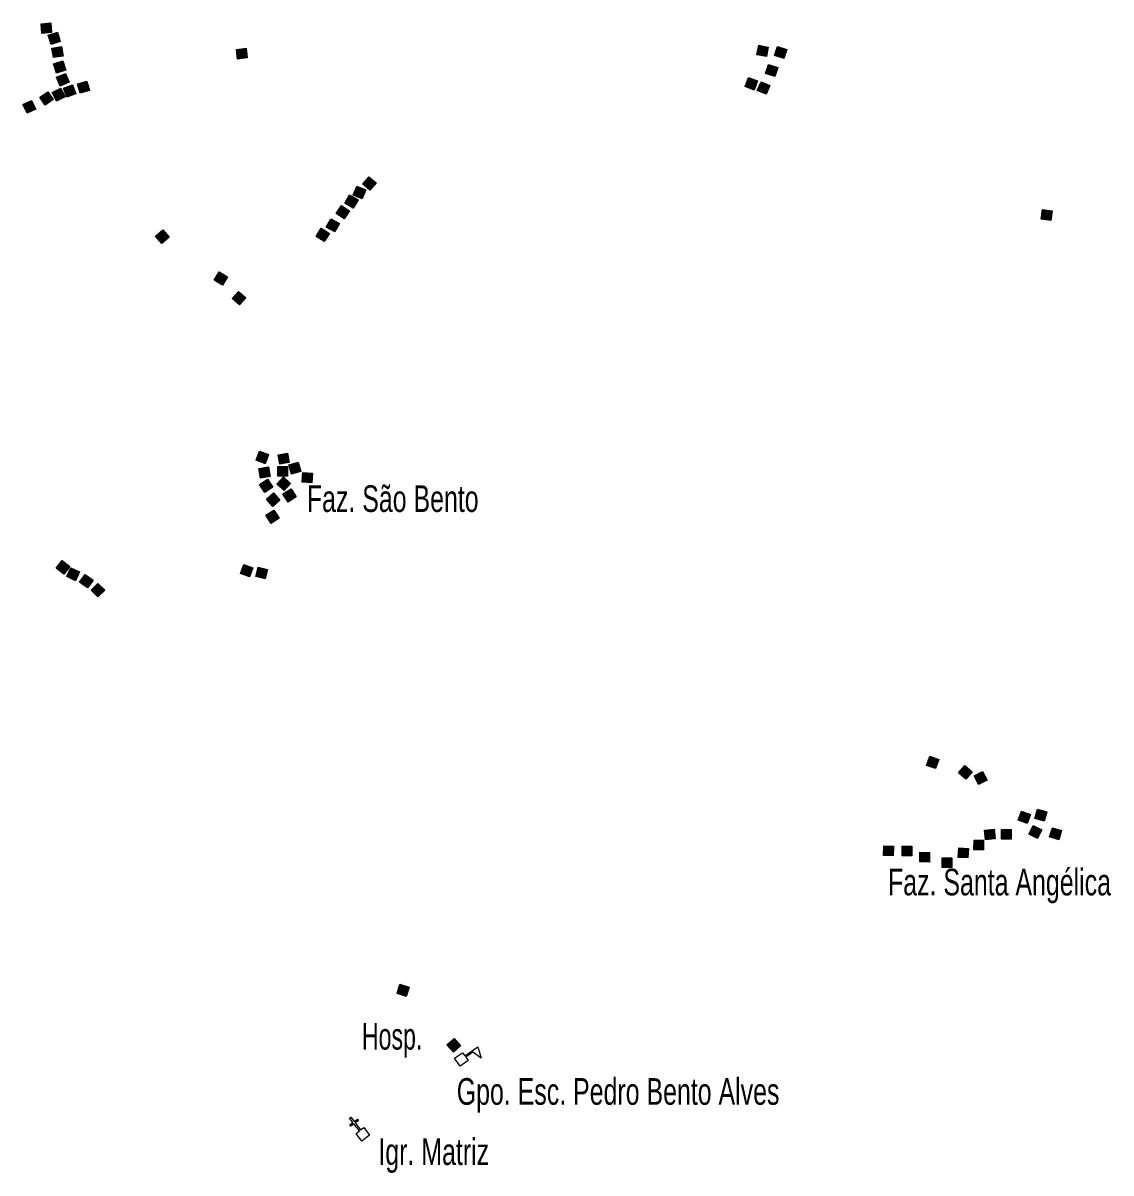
# Model space of a CAD drawing. Extents: x 679 to 705, y 7427.4 to 7455.4.
# Drawn here: x 698.263 to 701.533, y 7440.1 to 7443.555 of the extents above; entities that cross this region are included whole.
import ezdxf

# ---------------------------------------------------------------- set-up
doc = ezdxf.new("R2010")
doc.units = 0
doc.header["$LTSCALE"] = 0.032
for name, color, linetype, lineweight in [('2', 7, 'Continuous', 25), ('4', 7, 'Continuous', 25), ('6', 7, 'Continuous', 25)]:
    doc.layers.add(name, color=color, linetype=linetype, lineweight=lineweight)
doc.layers.add('61', color=7, linetype='Continuous')

msp = doc.modelspace()

# ---------------------------------------------------------------- hatches: boundary and pattern name
at = {"layer": '2'}
for points in [[(698.3468, 7443.5551), (698.3489, 7443.5261), (698.32, 7443.524), (698.3178, 7443.5529)], [(698.3672, 7443.5271), (698.3755, 7443.4992), (698.3477, 7443.491), (698.3394, 7443.5188)], [(698.3788, 7443.4843), (698.3836, 7443.4557), (698.355, 7443.451), (698.3502, 7443.4796)], [(698.9339, 7443.479), (698.9373, 7443.4502), (698.9085, 7443.4468), (698.9051, 7443.4756)], [(700.5033, 7443.4826), (700.4977, 7443.4542), (700.4692, 7443.4598), (700.4749, 7443.4882)], [(700.5587, 7443.4759), (700.5498, 7443.4483), (700.5222, 7443.4572), (700.5311, 7443.4848)], [(698.3826, 7443.4412), (698.3918, 7443.4137), (698.3643, 7443.4045), (698.3551, 7443.432)], [(700.5316, 7443.4216), (700.5227, 7443.394), (700.4951, 7443.403), (700.504, 7443.4306)], [(698.3906, 7443.4036), (698.4021, 7443.377), (698.3755, 7443.3654), (698.364, 7443.392)], [(700.4714, 7443.381), (700.4613, 7443.3538), (700.4341, 7443.3639), (700.4442, 7443.3911)], [(698.3767, 7443.3593), (698.3899, 7443.3335), (698.3641, 7443.3203), (698.3509, 7443.346)], [(698.4123, 7443.3697), (698.4224, 7443.3425), (698.3953, 7443.3324), (698.3851, 7443.3595)], [(698.4552, 7443.3802), (698.463, 7443.3523), (698.4351, 7443.3444), (698.4272, 7443.3723)], [(700.5084, 7443.3675), (700.4971, 7443.3408), (700.4704, 7443.352), (700.4817, 7443.3788)], [(698.2893, 7443.3225), (698.3021, 7443.2964), (698.276, 7443.2837), (698.2633, 7443.3098)], [(698.3375, 7443.3487), (698.354, 7443.3249), (698.3302, 7443.3084), (698.3137, 7443.3322)], [(699.3029, 7443.0934), (699.3249, 7443.0746), (699.306, 7443.0525), (699.284, 7443.0714)], [(699.2667, 7443.0648), (699.2935, 7443.0537), (699.2823, 7443.0269), (699.2555, 7443.0381)], [(699.245, 7443.0385), (699.2702, 7443.0242), (699.2559, 7442.999), (699.2307, 7443.0133)], [(699.2209, 7443.007), (699.245, 7442.9908), (699.2288, 7442.9667), (699.2047, 7442.9829)], [(701.3565, 7442.9903), (701.3525, 7442.9616), (701.3238, 7442.9656), (701.3278, 7442.9943)], [(699.1889, 7442.9666), (699.2143, 7442.9526), (699.2003, 7442.9272), (699.1749, 7442.9412)], [(698.6839, 7442.9339), (698.7028, 7442.912), (698.6809, 7442.893), (698.6619, 7442.915)], [(699.1597, 7442.9382), (699.1843, 7442.9228), (699.1688, 7442.8982), (699.1443, 7442.9137)], [(698.8533, 7442.8073), (698.8781, 7442.7922), (698.863, 7442.7675), (698.8382, 7442.7826)], [(698.9108, 7442.7488), (698.9326, 7442.7298), (698.9136, 7442.7079), (698.8917, 7442.727)], [(699.0012, 7442.2582), (698.9909, 7442.2311), (698.9638, 7442.2414), (698.9741, 7442.2685)], [(699.0584, 7442.2628), (699.0633, 7442.2342), (699.0348, 7442.2293), (699.0298, 7442.2578)], [(699.001, 7442.2213), (699.0059, 7442.1927), (698.9773, 7442.1878), (698.9724, 7442.2164)], [(699.0578, 7442.2224), (699.0578, 7442.1934), (699.0288, 7442.1934), (699.0288, 7442.2224)], [(699.0901, 7442.2352), (699.0981, 7442.2073), (699.0702, 7442.1993), (699.0622, 7442.2272)], [(698.9981, 7442.1845), (699.0145, 7442.1606), (698.9906, 7442.1442), (698.9742, 7442.1681)], [(699.0465, 7442.1912), (699.0677, 7442.1714), (699.0479, 7442.1502), (699.0267, 7442.17)], [(699.1336, 7442.2023), (699.1317, 7442.1734), (699.1027, 7442.1753), (699.1047, 7442.2043)], [(699.069, 7442.1557), (699.0845, 7442.1312), (699.0599, 7442.1157), (699.0445, 7442.1402)], [(699.0164, 7442.1433), (699.0357, 7442.1217), (699.014, 7442.1024), (698.9947, 7442.124)], [(699.0176, 7442.0919), (699.0335, 7442.0677), (699.0093, 7442.0518), (698.9934, 7442.076)], [(698.381, 7441.9401), (698.4038, 7441.9221), (698.3858, 7441.8994), (698.363, 7441.9173)], [(698.4071, 7441.9183), (698.4333, 7441.9058), (698.4208, 7441.8796), (698.3946, 7441.8921)], [(698.9544, 7441.9178), (698.944, 7441.8908), (698.917, 7441.9012), (698.9274, 7441.9282)], [(698.998, 7441.9134), (698.9908, 7441.8853), (698.9627, 7441.8926), (698.97, 7441.9206)], [(698.4505, 7441.8985), (698.4739, 7441.8813), (698.4567, 7441.858), (698.4333, 7441.8751)], [(698.4885, 7441.8716), (698.509, 7441.8511), (698.4885, 7441.8306), (698.468, 7441.8511)], [(701.0157, 7441.3423), (701.006, 7441.315), (700.9787, 7441.3247), (700.9884, 7441.352)], [(701.0941, 7441.3243), (701.1158, 7441.3051), (701.0967, 7441.2834), (701.0749, 7441.3026)], [(701.1475, 7441.306), (701.1607, 7441.2802), (701.1349, 7441.267), (701.1217, 7441.2928)], [(701.2913, 7441.1775), (701.2815, 7441.1502), (701.2542, 7441.16), (701.264, 7441.1873)], [(701.3402, 7441.1849), (701.3321, 7441.157), (701.3042, 7441.1652), (701.3124, 7441.193)], [(701.3257, 7441.1307), (701.3127, 7441.1047), (701.2868, 7441.1177), (701.2998, 7441.1436)], [(701.1821, 7441.1332), (701.1854, 7441.1044), (701.1566, 7441.1011), (701.1533, 7441.1299)], [(701.2332, 7441.1318), (701.2332, 7441.1028), (701.2042, 7441.1028), (701.2042, 7441.1318)], [(701.3849, 7441.1289), (701.3765, 7441.1011), (701.3488, 7441.1095), (701.3572, 7441.1373)], [(700.8798, 7441.0818), (700.8787, 7441.0528), (700.8497, 7441.0539), (700.8508, 7441.0829)], [(700.9351, 7441.0823), (700.9351, 7441.0533), (700.9061, 7441.0533), (700.9061, 7441.0823)], [(701.1046, 7441.0754), (701.1035, 7441.0465), (701.0745, 7441.0475), (701.0756, 7441.0765)], [(701.1506, 7441.0995), (701.1499, 7441.0705), (701.1209, 7441.0713), (701.1217, 7441.1003)], [(700.9879, 7441.0629), (700.9874, 7441.0339), (700.9584, 7441.0345), (700.9589, 7441.0635)], [(701.0546, 7441.0472), (701.0546, 7441.0182), (701.0256, 7441.0182), (701.0256, 7441.0472)], [(699.4237, 7440.6584), (699.4152, 7440.6307), (699.3875, 7440.6392), (699.396, 7440.6669)], [(699.559, 7440.5041), (699.5784, 7440.4825), (699.5568, 7440.4632), (699.5374, 7440.4848)]]:
    msp.add_hatch(color=256, dxfattribs=at).paths.add_polyline_path(points)

# ---------------------------------------------------------------- linework, layer by layer
for points in [[(698.3468, 7443.5551), (698.3489, 7443.5261), (698.32, 7443.524), (698.3178, 7443.5529)], [(698.3672, 7443.5271), (698.3755, 7443.4992), (698.3477, 7443.491), (698.3394, 7443.5188)], [(698.3788, 7443.4843), (698.3836, 7443.4557), (698.355, 7443.451), (698.3502, 7443.4796)], [(698.9339, 7443.479), (698.9373, 7443.4502), (698.9085, 7443.4468), (698.9051, 7443.4756)], [(700.5033, 7443.4826), (700.4977, 7443.4542), (700.4692, 7443.4598), (700.4749, 7443.4882)], [(700.5587, 7443.4759), (700.5498, 7443.4483), (700.5222, 7443.4572), (700.5311, 7443.4848)], [(698.3826, 7443.4412), (698.3918, 7443.4137), (698.3643, 7443.4045), (698.3551, 7443.432)], [(700.5316, 7443.4216), (700.5227, 7443.394), (700.4951, 7443.403), (700.504, 7443.4306)], [(698.3906, 7443.4036), (698.4021, 7443.377), (698.3755, 7443.3654), (698.364, 7443.392)], [(700.4714, 7443.381), (700.4613, 7443.3538), (700.4341, 7443.3639), (700.4442, 7443.3911)], [(698.3767, 7443.3593), (698.3899, 7443.3335), (698.3641, 7443.3203), (698.3509, 7443.346)], [(698.4123, 7443.3697), (698.4224, 7443.3425), (698.3953, 7443.3324), (698.3851, 7443.3595)], [(698.4552, 7443.3802), (698.463, 7443.3523), (698.4351, 7443.3444), (698.4272, 7443.3723)], [(700.5084, 7443.3675), (700.4971, 7443.3408), (700.4704, 7443.352), (700.4817, 7443.3788)], [(698.2893, 7443.3225), (698.3021, 7443.2964), (698.276, 7443.2837), (698.2633, 7443.3098)], [(698.3375, 7443.3487), (698.354, 7443.3249), (698.3302, 7443.3084), (698.3137, 7443.3322)], [(699.3029, 7443.0934), (699.3249, 7443.0746), (699.306, 7443.0525), (699.284, 7443.0714)], [(699.2667, 7443.0648), (699.2935, 7443.0537), (699.2823, 7443.0269), (699.2555, 7443.0381)], [(699.245, 7443.0385), (699.2702, 7443.0242), (699.2559, 7442.999), (699.2307, 7443.0133)], [(699.2209, 7443.007), (699.245, 7442.9908), (699.2288, 7442.9667), (699.2047, 7442.9829)], [(701.3565, 7442.9903), (701.3525, 7442.9616), (701.3238, 7442.9656), (701.3278, 7442.9943)], [(699.1889, 7442.9666), (699.2143, 7442.9526), (699.2003, 7442.9272), (699.1749, 7442.9412)], [(698.6839, 7442.9339), (698.7028, 7442.912), (698.6809, 7442.893), (698.6619, 7442.915)], [(699.1597, 7442.9382), (699.1843, 7442.9228), (699.1688, 7442.8982), (699.1443, 7442.9137)], [(698.8533, 7442.8073), (698.8781, 7442.7922), (698.863, 7442.7675), (698.8382, 7442.7826)], [(698.9108, 7442.7488), (698.9326, 7442.7298), (698.9136, 7442.7079), (698.8917, 7442.727)], [(699.0012, 7442.2582), (698.9909, 7442.2311), (698.9638, 7442.2414), (698.9741, 7442.2685)], [(699.0584, 7442.2628), (699.0633, 7442.2342), (699.0348, 7442.2293), (699.0298, 7442.2578)], [(699.001, 7442.2213), (699.0059, 7442.1927), (698.9773, 7442.1878), (698.9724, 7442.2164)], [(699.0578, 7442.2224), (699.0578, 7442.1934), (699.0288, 7442.1934), (699.0288, 7442.2224)], [(699.0901, 7442.2352), (699.0981, 7442.2073), (699.0702, 7442.1993), (699.0622, 7442.2272)], [(698.9981, 7442.1845), (699.0145, 7442.1606), (698.9906, 7442.1442), (698.9742, 7442.1681)], [(699.0465, 7442.1912), (699.0677, 7442.1714), (699.0479, 7442.1502), (699.0267, 7442.17)], [(699.1336, 7442.2023), (699.1317, 7442.1734), (699.1027, 7442.1753), (699.1047, 7442.2043)], [(699.069, 7442.1557), (699.0845, 7442.1312), (699.0599, 7442.1157), (699.0445, 7442.1402)], [(699.0164, 7442.1433), (699.0357, 7442.1217), (699.014, 7442.1024), (698.9947, 7442.124)], [(699.0176, 7442.0919), (699.0335, 7442.0677), (699.0093, 7442.0518), (698.9934, 7442.076)], [(698.381, 7441.9401), (698.4038, 7441.9221), (698.3858, 7441.8994), (698.363, 7441.9173)], [(698.4071, 7441.9183), (698.4333, 7441.9058), (698.4208, 7441.8796), (698.3946, 7441.8921)], [(698.9544, 7441.9178), (698.944, 7441.8908), (698.917, 7441.9012), (698.9274, 7441.9282)], [(698.998, 7441.9134), (698.9908, 7441.8853), (698.9627, 7441.8926), (698.97, 7441.9206)], [(698.4505, 7441.8985), (698.4739, 7441.8813), (698.4567, 7441.858), (698.4333, 7441.8751)], [(698.4885, 7441.8716), (698.509, 7441.8511), (698.4885, 7441.8306), (698.468, 7441.8511)], [(701.0157, 7441.3423), (701.006, 7441.315), (700.9787, 7441.3247), (700.9884, 7441.352)], [(701.0941, 7441.3243), (701.1158, 7441.3051), (701.0967, 7441.2834), (701.0749, 7441.3026)], [(701.1475, 7441.306), (701.1607, 7441.2802), (701.1349, 7441.267), (701.1217, 7441.2928)], [(701.2913, 7441.1775), (701.2815, 7441.1502), (701.2542, 7441.16), (701.264, 7441.1873)], [(701.3402, 7441.1849), (701.3321, 7441.157), (701.3042, 7441.1652), (701.3124, 7441.193)], [(701.3257, 7441.1307), (701.3127, 7441.1047), (701.2868, 7441.1177), (701.2998, 7441.1436)], [(701.1821, 7441.1332), (701.1854, 7441.1044), (701.1566, 7441.1011), (701.1533, 7441.1299)], [(701.2332, 7441.1318), (701.2332, 7441.1028), (701.2042, 7441.1028), (701.2042, 7441.1318)], [(701.3849, 7441.1289), (701.3765, 7441.1011), (701.3488, 7441.1095), (701.3572, 7441.1373)], [(700.8798, 7441.0818), (700.8787, 7441.0528), (700.8497, 7441.0539), (700.8508, 7441.0829)], [(700.9351, 7441.0823), (700.9351, 7441.0533), (700.9061, 7441.0533), (700.9061, 7441.0823)], [(701.1046, 7441.0754), (701.1035, 7441.0465), (701.0745, 7441.0475), (701.0756, 7441.0765)], [(701.1506, 7441.0995), (701.1499, 7441.0705), (701.1209, 7441.0713), (701.1217, 7441.1003)], [(700.9879, 7441.0629), (700.9874, 7441.0339), (700.9584, 7441.0345), (700.9589, 7441.0635)], [(701.0546, 7441.0472), (701.0546, 7441.0182), (701.0256, 7441.0182), (701.0256, 7441.0472)], [(699.4237, 7440.6584), (699.4152, 7440.6307), (699.3875, 7440.6392), (699.396, 7440.6669)], [(699.559, 7440.5041), (699.5784, 7440.4825), (699.5568, 7440.4632), (699.5374, 7440.4848)]]:
    msp.add_lwpolyline(points, close=True, dxfattribs=at)
at = {"layer": '4'}
for points in [[(699.5938, 7440.4475), (699.6008, 7440.4376), (699.5771, 7440.4209), (699.5604, 7440.4446), (699.5841, 7440.4613), (699.591, 7440.4515)], [(699.591, 7440.4515), (699.6305, 7440.4794), (699.6406, 7440.445), (699.6151, 7440.4626), (699.5938, 7440.4475)]]:
    msp.add_lwpolyline(points, dxfattribs=at)
at = {"layer": '6'}
for points in [[(699.2742, 7440.2263), (699.2578, 7440.2478), (699.2482, 7440.2405), (699.2452, 7440.2444), (699.2549, 7440.2517), (699.2449, 7440.2648), (699.2488, 7440.2677), (699.2587, 7440.2547), (699.2683, 7440.262), (699.2713, 7440.2581), (699.2617, 7440.2508), (699.2781, 7440.2292)], [(699.2781, 7440.2292), (699.2877, 7440.2365), (699.3052, 7440.2134), (699.2822, 7440.1959), (699.2646, 7440.219), (699.2742, 7440.2263)]]:
    msp.add_lwpolyline(points, dxfattribs=at)

# ---------------------------------------------------------------- texts
at = {"layer": '61'}
for s, width, p in [('Faz. São Bento', 0.7, (699.1165, 7442.0861)), ('Faz. Santa Angélica', 0.7, (700.8632, 7440.934)), ('Hosp.', 0.65, (699.2819, 7440.4708)), ('Gpo. Esc. Pedro Bento Alves', 0.7, (699.567, 7440.305)), ('Igr. Matriz', 0.7, (699.3315, 7440.1241))]:
    msp.add_text(s, height=0.08, dxfattribs=dict(at, width=width)).set_placement(p)

doc.saveas('drawing.dxf')
